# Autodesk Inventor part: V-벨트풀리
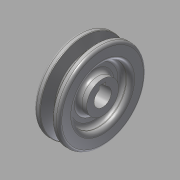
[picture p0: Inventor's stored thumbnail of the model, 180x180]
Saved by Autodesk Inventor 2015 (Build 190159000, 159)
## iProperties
Created: 2015-12
Part Number: V-벨트풀리
Material: 강철, 연강
Document SubType Name: Modeling
Designer: mduedu
Density: 7.86 g/cm^3
Appearance: 강철
Author: mduedu
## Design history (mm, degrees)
sketch "스케치1"
  geometry: L1 (-9.5, 0)-(9.5, 0); L2 (-9.5, 0)-(-9.5, 32.7); L3 (-9.5, 32.7)-(-4.825, 32.7); L4 (-4.825, 32.7)-(-2.074, 23.7); L5 (-2.074, 23.7)-(0, 23.7); L6 (0, 0)-(0, 23.7); L7 (9.5, 0)-(9.5, 32.7); L8 (9.5, 32.7)-(4.825, 32.7); L9 (4.825, 32.7)-(2.074, 23.7); L10 (2.074, 23.7)-(0, 23.7); L11 (-4, 30)-(4, 30); 3 further points
  constraints: 22 end point, 3 coincident, 3 perpendicular, 3 symmetric about line, 2 parallel, 2 point on line, 1 horizontal, 1 midpoint, 1 vertical alignment
  dimensions: "d0" = 19 distance between parallel lines of L7 L2; "d2" = 6.3 distance between parallel lines of L10 L11; "d3" = 34 deg angle of L9 L4; "d4" = 2.7 distance between parallel lines of L11 L8; "d5" = 60 diameter of L11 L1; "d6" = 8 distance of L11.end L11.start
revolve "회전1" sketch "스케치1" stored, may be unused: angle "d7" = 90 deg
sketch "스케치2"
  geometry: C1 r 21 at (0, 0); C2 r 12 at (0, 0); 1 further point
  constraints: 2 centre point, 2 coincident
  dimensions: "d8" = 42 diameter of C1; "d10" = 24 diameter of C2
extrude "돌출1" cut sketch "스케치2" distance "d11" = 6.5; taper "d12" = 0 deg
fillet "모깎기1" dims "d13" = 1, "d14" = 0.5, "d15" = 2
fillet "모깎기2" dims "d16" = 3
fillet "모깎기3" dims "d17" = 3
hole "구멍1" diameter "d20" = 13; stored, may be unused: countersink angle "d24" = 90 deg, drill point angle "d26" = 118 deg; dims "d18" = 10, "d19" = 10, "d21" = 6, "d22" = 4, "d23" = 2, "d25" = 8
sketch "스케치3"
  geometry: L1 (-2.5, 0)-(2.5, 0); L2 (2.5, 0)-(2.5, 8.8); L3 (2.5, 8.8)-(-2.5, 8.8); L4 (-2.5, 8.8)-(-2.5, 0); 2 further points
  constraints: 8 end point, 2 parallel, 1 coincident, 1 horizontal, 1 midpoint, 1 perpendicular
  dimensions: "d27" = 8.8 distance of L1.end L2.end; "d29" = 5 distance of L2.end L3.end
extrude "돌출2" cut sketch "스케치3" stored distance "d30" = 6.5; taper "d31" = 0 deg
node "솔리드1"
mirror "대칭1"
